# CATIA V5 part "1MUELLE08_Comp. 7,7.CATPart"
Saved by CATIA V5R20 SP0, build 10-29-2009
Part number: 1MUELLE08_Comp. 7,7
Revision: ANY
Definition: UNKNOWN
Nomenclature: 1MUELLE08_Comp. 7,7
Source: Unknown
Bounding box of the stored display mesh (mm): x -5.85 to 5.85, y -5.85 to 5.85, z -0.6 to 8.299
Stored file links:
  C:\Users\Utente\Desktop\IO LAVORO\3D X SITO CF\CUMSA\3D files AE\AE 082430\1MUELLE08_Comp. 7,7.CATPart
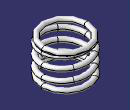
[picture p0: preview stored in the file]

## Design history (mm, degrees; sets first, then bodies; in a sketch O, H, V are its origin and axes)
Set1 "FacciaKO#NONE#23013"
  DatumSurface1 "Sup23013_1"
  Circle1 "Crv23013_1": stored without definition
Set2 "FacciaKO#NONE#16513"
  DatumSurface2 "Sup16513_1"
  Circle2 "Crv16513_1": stored without definition
Set3 "FacciaKO#NONE#8645"
  DatumSurface3 "Sup8645_1"
  Circle3 "Crv8645_1": stored without definition
Set4 "FacciaKO#NONE#11011"
  DatumSurface4 "Sup11011_1"
  Circle4 "Crv11011_1": stored without definition
Body1 "Cortar-Extruir3" (main body)
  Solid1: solid without history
